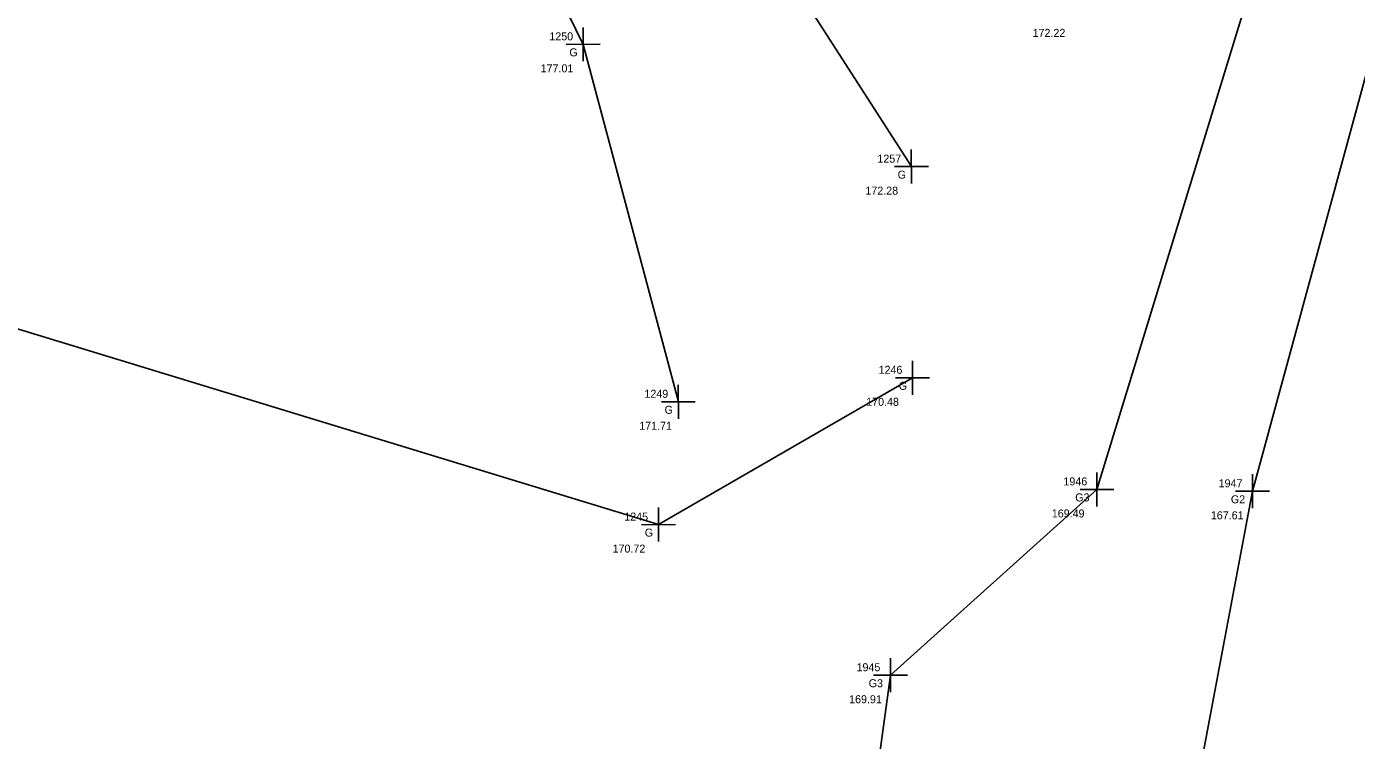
# Model space of a CAD drawing. Extents: x 1157913 to 1159198, y 600595 to 601244.
# Drawn here: x 1158460.89 to 1158510.75, y 600875.3 to 600902.06 of the extents above; entities that cross this region are included whole.
import ezdxf

# ---------------------------------------------------------------- set-up
doc = ezdxf.new("R2010")
doc.units = 0
for name, color, linetype in [('S_Field_Code', 7, 'Continuous'), ('S_Ground_Elevation', 7, 'Continuous'), ('S_Point_Elevation', 7, 'Continuous'), ('S_Point_Name', 7, 'Continuous'), ('S_Survey_Shot', 7, 'Continuous')]:
    doc.layers.add(name, color=color, linetype=linetype)

msp = doc.modelspace()

# ---------------------------------------------------------------- linework, layer by layer
at = {"layer": 'S_Ground_Elevation'}
for points in [[(1158456.725, 600634.912), (1158466.02, 600684.687), (1158480.163, 600740.538), (1158489.787, 600796.42), (1158500.682, 600851.861), (1158506.861, 600884.636), (1158514.351, 600912.17), (1158520.904, 600948.119), (1158528.212, 600980.906), (1158534.593, 601016.588), (1158540.159, 601049.077), (1158546.142, 601074.619), (1158552.335, 601110.789), (1158554.11, 601121.634), (1158561.634, 601157.31), (1158572.878, 601226.421), (1158576.278, 601242.453)], [(1158247.665, 600949.536), (1158269.961, 600945.775), (1158291.402, 600940.703), (1158317.511, 600934.427), (1158338.149, 600927.985), (1158356.293, 600925.433), (1158398.265, 600912.716), (1158421.932, 600903.38), (1158459.675, 600890.989), (1158484.586, 600883.387), (1158494.108, 600888.89)], [(1158485.328, 600887.991), (1158481.758, 600901.391), (1158476.618, 600911.911), (1158469.082, 600918.035), (1158466.342, 600919.595)], [(1158472.24, 600919.876), (1158479.736, 600915.08), (1158487.585, 600906.896), (1158494.065, 600896.807)], [(1158417.202, 600659.944), (1158425.519, 600653.573), (1158433.344, 600650.427), (1158437.71, 600654.503), (1158444.811, 600658.736), (1158451.283, 600687.753), (1158462.34, 600743.775), (1158474.252, 600798.648), (1158489.994, 600853.766), (1158493.281, 600877.741), (1158501.025, 600884.706), (1158509.554, 600912.567)]]:
    msp.add_lwpolyline(points, dxfattribs=at)
at = {"layer": 'S_Survey_Shot'}
for p, q in [((1158481.76, 600900.755), (1158481.757, 600902.027)), ((1158481.122, 600901.39), (1158482.395, 600901.392)), ((1158481.758, 600901.391), (1158481.758, 600901.391)), ((1158494.067, 600896.171), (1158494.064, 600897.443)), ((1158493.429, 600896.806), (1158494.702, 600896.808)), ((1158494.065, 600896.807), (1158494.065, 600896.807)), ((1158494.109, 600888.254), (1158494.106, 600889.526)), ((1158485.33, 600887.355), (1158485.327, 600888.628)), ((1158493.471, 600888.889), (1158494.744, 600888.891)), ((1158494.108, 600888.89), (1158494.108, 600888.89)), ((1158484.692, 600887.99), (1158485.964, 600887.993)), ((1158485.328, 600887.991), (1158485.328, 600887.991)), ((1158501.026, 600884.07), (1158501.024, 600885.342)), ((1158506.863, 600884), (1158506.86, 600885.272)), ((1158500.389, 600884.705), (1158501.661, 600884.707)), ((1158501.025, 600884.706), (1158501.025, 600884.706)), ((1158506.225, 600884.635), (1158507.497, 600884.638)), ((1158506.861, 600884.636), (1158506.861, 600884.636)), ((1158484.587, 600882.75), (1158484.585, 600884.023)), ((1158483.95, 600883.385), (1158485.222, 600883.388)), ((1158484.586, 600883.387), (1158484.586, 600883.387)), ((1158493.282, 600877.105), (1158493.28, 600878.377)), ((1158492.645, 600877.74), (1158493.917, 600877.742)), ((1158493.281, 600877.741), (1158493.281, 600877.741))]:
    msp.add_line(p, q, dxfattribs=at)

# ---------------------------------------------------------------- texts
at = {"layer": 'S_Field_Code'}
for s, p in [('G', (1158481.243, 600900.941)), ('G', (1158493.551, 600896.357)), ('G', (1158493.593, 600888.44)), ('G', (1158484.813, 600887.541)), ('G3', (1158500.21, 600884.256)), ('G2', (1158506.046, 600884.186)), ('G', (1158484.071, 600882.937)), ('G3', (1158492.466, 600877.291))]:
    msp.add_text(s, height=0.3, dxfattribs=at).set_placement(p)
at = {"layer": 'S_Point_Elevation'}
for s, p in [('172.22', (1158498.612, 600901.671)), ('177.01', (1158480.164, 600900.341)), ('172.28', (1158492.341, 600895.757)), ('170.48', (1158492.372, 600887.84)), ('171.71', (1158483.862, 600886.941)), ('169.49', (1158499.332, 600883.656)), ('167.61', (1158505.296, 600883.586)), ('170.72', (1158482.862, 600882.337)), ('169.91', (1158491.732, 600876.691))]:
    msp.add_text(s, height=0.3, dxfattribs=at).set_placement(p)
at = {"layer": 'S_Point_Name'}
for s, p in [('1250', (1158480.49, 600901.541)), ('1257', (1158492.792, 600896.957)), ('1246', (1158492.837, 600889.04)), ('1249', (1158484.057, 600888.141)), ('1946', (1158499.768, 600884.856)), ('1947', (1158505.588, 600884.786)), ('1245', (1158483.301, 600883.537)), ('1945', (1158492.01, 600877.891))]:
    msp.add_text(s, height=0.3, dxfattribs=at).set_placement(p)

doc.saveas('drawing.dxf')
